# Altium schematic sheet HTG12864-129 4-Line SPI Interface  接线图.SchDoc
size A4
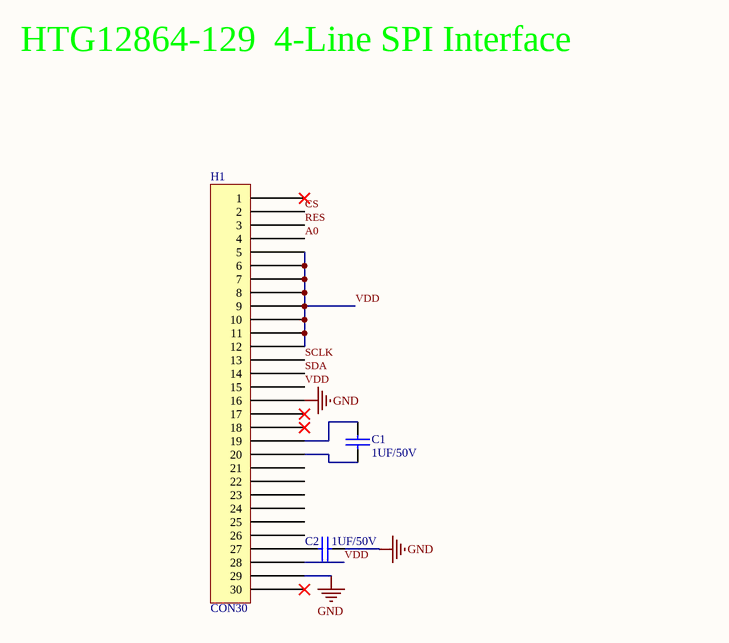
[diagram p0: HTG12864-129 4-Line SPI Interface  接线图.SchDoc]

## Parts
C1  1UF/50V
C2  1UF/50V
H1  CON30

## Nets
GND: C2.2 H1.16 H1.29
A0: H1.4
CS: H1.2
RES: H1.3
SCLK: H1.13
SDA: H1.14
VDD: H1.5 H1.6 H1.7 H1.8 H1.9 H1.10 H1.11 H1.12 H1.15 H1.28
NetC1_1: C1.1 H1.19
NetC1_2: C1.2 H1.20
NetC2_1: C2.1 H1.27

Not connected (* = marked no-connect by the designer): H1 1* 17* 18* 21 22 23 24 25 26 30*

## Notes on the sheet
- HTG12864-129  4-Line SPI Interface

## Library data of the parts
C1 C2 = CAP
